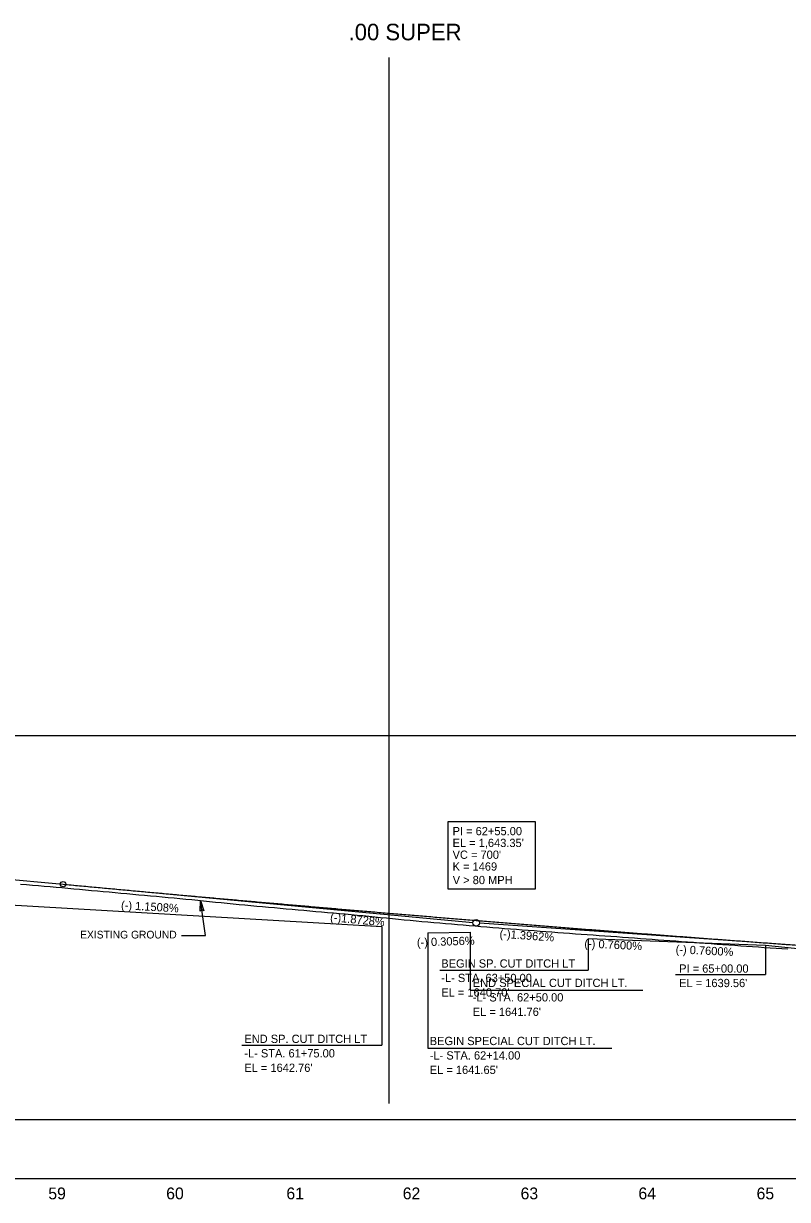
# Model space of a CAD drawing. Extents: x 498575 to 532350, y 405181 to 484585.
# Drawn here: x 510691 to 511338, y 483216 to 484213 of the extents above; entities that cross this region are included whole.
import ezdxf

# ---------------------------------------------------------------- set-up
doc = ezdxf.new("R2010")
doc.units = 0
for name, color, linetype in [('Exist Profile Cell', 7, 'Continuous'), ('Exist Vertical Profile Ground Line', 7, 'Continuous'), ('Exist Vertical Profile Horizontal Axis Label Major', 7, 'Continuous'), ('Prop Grid Mask', 7, 'Continuous'), ('Prop PFL Text', 7, 'Continuous'), ('Prop Vertical Profile Curve Label', 7, 'Continuous'), ('Prop Vertical Profile Ditch Grade Left', 7, 'Continuous'), ('Prop Vertical Profile Ditch Grade Left Label', 7, 'Continuous'), ('Prop Vertical Profile Grade', 7, 'Continuous'), ('Prop Vertical Profile Grade Label', 7, 'Continuous'), ('Prop VPI Label', 7, 'Continuous'), ('Scratch_Level_3', 7, 'Continuous'), ('Scratch_Level_4', 7, 'Continuous'), ('Scratch_Level_5', 7, 'Continuous')]:
    doc.layers.add(name, color=color, linetype=linetype)

msp = doc.modelspace()

# ---------------------------------------------------------------- linework, layer by layer
at = {"layer": 'Exist Profile Cell'}
msp.add_line((505856.74, 483233.71), (526056.74, 483233.71), dxfattribs=at)
at = {"layer": 'Exist Vertical Profile Ground Line'}
for points in [[(510688.15, 483483.33), (510693.15, 483482.89), (510698.15, 483482.47), (510703.15, 483482.03), (510708.15, 483481.62), (510713.15, 483481.2), (510718.15, 483480.75), (510723.15, 483480.3), (510728.15, 483479.87), (510733.15, 483479.38), (510738.15, 483478.93), (510743.15, 483478.51), (510748.15, 483478.02), (510753.15, 483477.58), (510758.15, 483477.15), (510763.15, 483476.67), (510768.15, 483476.24), (510773.15, 483475.74), (510778.15, 483475.26), (510783.15, 483474.8), (510788.15, 483474.31), (510793.15, 483473.85), (510798.15, 483473.4), (510803.15, 483472.96), (510808.15, 483472.51), (510813.15, 483472.07)], [(510813.15, 483472.07), (510818.15, 483471.61), (510823.15, 483471.15), (510828.15, 483470.68), (510833.15, 483470.14), (510838.15, 483469.66), (510843.15, 483469.14), (510848.15, 483468.62), (510853.15, 483468.11), (510858.15, 483467.61), (510863.15, 483467.1), (510868.15, 483466.61), (510873.15, 483466.16), (510878.15, 483465.65), (510883.15, 483465.17), (510888.15, 483464.72), (510893.15, 483464.26), (510898.15, 483463.83), (510903.15, 483463.36), (510908.15, 483462.95), (510913.15, 483462.49), (510918.15, 483462.02), (510923.15, 483461.56), (510928.15, 483461.12), (510933.15, 483460.66), (510938.15, 483460.19), (510943.15, 483459.76), (510948.15, 483459.34), (510953.15, 483458.88), (510958.15, 483458.45), (510963.15, 483458.01), (510968.15, 483457.56), (510973.15, 483457.09), (510978.15, 483456.61), (510983.15, 483456.12), (510988.15, 483455.64), (510993.15, 483455.11), (510998.15, 483454.6), (511003.15, 483454.14), (511008.15, 483453.63), (511013.15, 483453.15), (511018.15, 483452.69), (511023.15, 483452.23), (511028.15, 483451.76), (511033.15, 483451.34), (511038.15, 483450.9), (511043.15, 483450.44), (511048.15, 483450.01), (511053.15, 483449.56), (511058.15, 483449.15), (511063.15, 483448.73), (511068.15, 483448.31), (511073.15, 483447.91), (511078.15, 483447.48), (511083.15, 483447.04), (511088.15, 483446.62), (511093.15, 483446.23), (511098.15, 483445.82), (511103.15, 483445.43), (511108.15, 483445.03), (511113.15, 483444.66), (511118.15, 483444.28), (511123.15, 483443.88), (511128.15, 483443.48), (511133.15, 483443.09), (511138.15, 483442.73), (511143.15, 483442.35), (511148.15, 483442.01), (511153.15, 483441.67), (511158.15, 483441.31), (511163.15, 483440.97), (511168.15, 483440.61), (511173.15, 483440.26), (511178.15, 483439.89), (511183.15, 483439.52), (511188.15, 483439.16), (511193.15, 483438.81), (511198.15, 483438.45), (511203.15, 483438.09), (511208.15, 483437.67), (511213.15, 483437.3), (511218.15, 483436.96), (511223.15, 483436.57), (511228.15, 483436.21), (511233.15, 483435.85), (511238.15, 483435.47), (511243.15, 483435.12), (511248.15, 483434.77), (511253.15, 483434.38), (511258.15, 483433.99), (511263.15, 483433.63), (511268.15, 483433.26), (511273.15, 483432.9), (511278.15, 483432.54), (511283.15, 483432.17), (511288.15, 483431.83), (511293.15, 483431.48), (511298.15, 483431.1), (511303.15, 483430.73), (511308.15, 483430.39), (511313.15, 483430.03)], [(511313.15, 483430.03), (511318.15, 483429.68), (511323.15, 483429.35), (511328.15, 483429.03), (511333.15, 483428.71), (511338.15, 483428.43)]]:
    msp.add_lwpolyline(points, dxfattribs=at)
at = {"layer": 'Prop Grid Mask'}
msp.add_lwpolyline([(511050.18, 483479.21), (511124.44, 483479.21), (511124.44, 483535.99), (511050.18, 483535.99)], close=True, dxfattribs=at)
at = {"layer": 'Prop PFL Text'}
for p, q in [((510844.78, 483439.79), (510840.65, 483469.41)), ((510824.42, 483439.79), (510844.78, 483439.79))]:
    msp.add_line(p, q, dxfattribs=at)
msp.add_lwpolyline([(510840.36, 483460.28), (510840.65, 483469.41), (510843.49, 483460.66), (510841.75, 483461.58)], close=True, dxfattribs=at)
at = {"layer": 'Prop Vertical Profile Curve Label'}
msp.add_circle((510724.08, 483483.24), 2.25, dxfattribs=at)
at = {"layer": 'Prop Vertical Profile Ditch Grade Left'}
for points in [[(510669.08, 483466.21), (510994.08, 483447.51), (510994.08, 483447.51)], [(511169.08, 483437.21), (511319.08, 483431.51), (511469.08, 483415.91), (511469.08, 483415.91)]]:
    msp.add_lwpolyline(points, dxfattribs=at)
at = {"layer": 'Prop Vertical Profile Ditch Grade Left Label'}
for p, q in [((510994.08, 483447.51), (510994.08, 483346.84)), ((511169.08, 483437.21), (511169.08, 483410.33)), ((511319.08, 483431.51), (511319.08, 483406.74)), ((511043.25, 483410.33), (511169.08, 483410.33)), ((511242.85, 483406.74), (511319.08, 483406.74)), ((510875.68, 483346.84), (510994.08, 483346.84))]:
    msp.add_line(p, q, dxfattribs=at)
at = {"layer": 'Prop Vertical Profile Grade'}
msp.add_line((510486.58, 483505.48), (510724.08, 483483.24), dxfattribs=at)
msp.add_spline([(510724.08, 483483.24), (510738.08, 483481.93), (510752.08, 483480.63), (510766.08, 483479.33), (510780.08, 483478.05), (510794.08, 483476.76), (510808.08, 483475.49), (510822.08, 483474.22), (510836.08, 483472.96), (510850.08, 483471.71), (510864.08, 483470.46), (510878.08, 483469.22), (510892.08, 483467.98), (510906.08, 483466.76), (510920.08, 483465.54), (510934.08, 483464.32), (510948.08, 483463.11), (510962.08, 483461.91), (510976.08, 483460.72), (510990.08, 483459.53), (511004.08, 483458.35), (511018.08, 483457.18), (511032.08, 483456.01), (511046.08, 483454.85), (511060.08, 483453.69), (511074.08, 483452.55), (511088.08, 483451.41), (511102.08, 483450.27), (511116.08, 483449.14), (511130.08, 483448.02), (511144.08, 483446.91), (511158.08, 483445.8), (511172.08, 483444.7), (511186.08, 483443.61), (511200.08, 483442.52), (511214.08, 483441.44), (511228.08, 483440.37), (511242.08, 483439.3), (511256.08, 483438.24), (511270.08, 483437.18), (511284.08, 483436.14), (511298.08, 483435.1), (511312.08, 483434.06), (511326.08, 483433.03), (511340.08, 483432.01), (511354.08, 483431), (511368.08, 483429.99), (511382.08, 483428.99), (511396.08, 483428), (511410.08, 483427.01), (511424.08, 483426.03)], degree=3, dxfattribs=at)
at = {"layer": 'Prop VPI Label'}
for p, q in [((510724.08, 483483.24), (511071.34, 483450.72)), ((511424.08, 483426.03), (511076.82, 483450.27))]:
    msp.add_line(p, q, dxfattribs=at)
msp.add_circle((511074.08, 483450.46), 2.75, dxfattribs=at)
at = {"layer": 'Scratch_Level_3'}
for p, q in [((511033.08, 483441.96), (511033.08, 483344.15)), ((511069.08, 483442.51), (511069.08, 483393.36)), ((511069.08, 483393.36), (511215.31, 483393.36)), ((511033.08, 483344.15), (511188.95, 483344.15))]:
    msp.add_line(p, q, dxfattribs=at)
msp.add_lwpolyline([(511033.08, 483441.96), (511069.08, 483442.51), (511069.08, 483442.51)], dxfattribs=at)
at = {"layer": 'Scratch_Level_4'}
for p, q in [((511000.12, 484183.71), (511000.12, 483297.42)), ((505856.74, 483283.71), (512195.09, 483283.71))]:
    msp.add_line(p, q, dxfattribs=at)
at = {"layer": 'Scratch_Level_5'}
msp.add_line((513582.6, 483608.99), (498575.1, 483608.99), dxfattribs=at)

# ---------------------------------------------------------------- texts
at = {"layer": 'Exist Vertical Profile Horizontal Axis Label Major'}
for s, p in [('59', (510711.59, 483216.21)), ('59', (510711.59, 483216.21)), ('60', (510811.46, 483216.21)), ('60', (510811.47, 483216.21)), ('61', (510913.31, 483216.21)), ('61', (510913.3, 483216.21)), ('62', (511011.85, 483216.21)), ('62', (511011.85, 483216.21)), ('63', (511111.69, 483216.21)), ('63', (511111.69, 483216.21)), ('64', (511211.53, 483216.21)), ('64', (511211.53, 483216.21)), ('65', (511311.62, 483216.21)), ('65', (511311.62, 483216.21))]:
    msp.add_text(s, height=10, dxfattribs=at).set_placement(p)
at = {"layer": 'Prop PFL Text'}
msp.add_text('EXISTING GROUND', height=6.5157, dxfattribs=at).set_placement((510738.55, 483437.24))
at = {"layer": 'Prop Vertical Profile Curve Label'}
for s, p in [("VC = 700'", (511054.08, 483504.72)), ('K = 1469', (511054.08, 483494.72)), ('V > 80 MPH ', (511054.2, 483483.28))]:
    msp.add_text(s, height=7, dxfattribs=at).set_placement(p)
at = {"layer": 'Prop Vertical Profile Ditch Grade Left Label'}
for s, rotation, p in [('(-) 1.1508%', 356.66677, (510773.06, 483462.12)), ('(-) 0.7600%', 357.26947, (511165.58, 483429.62)), ('(-) 0.7600%', 357.26947, (511242.93, 483424.66)), ('BEGIN SP. CUT DITCH LT', 360, (511044.52, 483412.55)), ('PI = 65+00.00', 360, (511246.03, 483408.26)), ('-L- STA. 63+50.00', 360, (511044.52, 483400.3)), ("EL = 1640.70'", 360, (511044.52, 483388.05)), ("EL = 1639.56'", 360, (511246.03, 483396.01)), ('END SP. CUT DITCH LT', 360, (510877.66, 483348.69)), ('-L- STA. 61+75.00', 360, (510877.66, 483336.44)), ("EL = 1642.76'", 360, (510877.66, 483324.19))]:
    msp.add_text(s, height=7, rotation=rotation, dxfattribs=at).set_placement(p)
at = {"layer": 'Prop Vertical Profile Grade Label'}
for s, rotation, p in [('(-)1.8728%', 354.65038, (510950.13, 483451.88)), ('(-)1.3962%', 356.0068, (511093.72, 483437.86))]:
    msp.add_text(s, height=7, rotation=rotation, dxfattribs=at).set_placement(p)
at = {"layer": 'Prop VPI Label'}
for s, p in [('PI = 62+55.00', (511054.08, 483524.72)), ("EL = 1,643.35'", (511054.08, 483514.72))]:
    msp.add_text(s, height=7, dxfattribs=at).set_placement(p)
at = {"layer": 'Scratch_Level_3'}
for s, rotation, p in [('(-) 0.3056%', 1.8579, (511023.96, 483430.42)), ('END SPECIAL CUT DITCH LT.', 360, (511071.2, 483396.1)), ('-L- STA. 62+50.00', 360, (511071.2, 483383.85)), ("EL = 1641.76'", 360, (511071.2, 483371.6)), ('BEGIN SPECIAL CUT DITCH LT.', 360, (511034.74, 483346.89)), ('-L- STA. 62+14.00', 360, (511034.74, 483334.64)), ("EL = 1641.65'", 360, (511034.74, 483322.39))]:
    msp.add_text(s, height=7, rotation=rotation, dxfattribs=at).set_placement(p)
at = {"layer": 'Scratch_Level_4'}
msp.add_text('.00 SUPER', height=14, dxfattribs=at).set_placement((510965.95, 484198.32))

doc.saveas('drawing.dxf')
